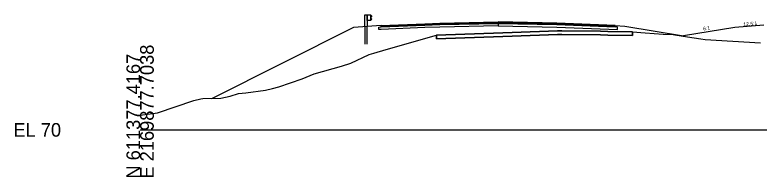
# Model space of a CAD drawing. Extents: x -26 to 1303, y -3010 to 12023.
# Drawn here: x 974.3 to 1127, y 4490.3 to 4523.6 of the extents above; entities that cross this region are included whole.
import ezdxf

# ---------------------------------------------------------------- set-up
doc = ezdxf.new("R2010")
doc.units = 0
for name, color, linetype in [('RD_GPK_XS_Cell', 7, 'Continuous'), ('RD_PD_Final_TrvlWay', 7, 'Continuous'), ('RD_XS_Base', 7, 'Continuous'), ('RD_XS_ExGround', 7, 'Continuous'), ('RD_XS_ExPaveRet', 7, 'Continuous'), ('RD_XS_GR', 7, 'Continuous'), ('RD_XS_Greenside', 7, 'Continuous'), ('RD_XS_Pave', 7, 'Continuous'), ('RD_XS_PaveOvlay_CP', 7, 'Continuous'), ('RD_XS_TieSlope', 7, 'Continuous'), ('RD_XS_TX_ShdSlope', 7, 'Continuous'), ('RD_XS_TX_Slope', 7, 'Continuous')]:
    doc.layers.add(name, color=color, linetype=linetype)

msp = doc.modelspace()

# ---------------------------------------------------------------- linework, layer by layer
at = {"layer": 'RD_GPK_XS_Cell'}
msp.add_line((1000, 4500), (1150, 4500), dxfattribs=at)
at = {"layer": 'RD_PD_Final_TrvlWay'}
msp.add_lwpolyline([(1046.58, 4517.58), (1046.58, 4521.19), (1046.08, 4521.15), (1046.08, 4517.58)], dxfattribs=at)
at = {"layer": 'RD_XS_Base'}
for p, q in [((1049.48, 4521.1), (1058.39, 4521.46)), ((1058.39, 4521.46), (1061.48, 4521.58)), ((1061.48, 4521.58), (1061.52, 4521.58)), ((1061.52, 4521.58), (1073.48, 4521.82)), ((1073.48, 4521.82), (1073.48, 4521.98)), ((1073.48, 4521.98), (1073.48, 4521.33)), ((1073.48, 4521.82), (1073.48, 4521.98)), ((1073.48, 4521.98), (1073.48, 4521.32)), ((1073.48, 4521.82), (1073.48, 4521.33)), ((1073.48, 4521.82), (1073.48, 4521.82)), ((1073.48, 4521.82), (1073.48, 4521.32)), ((1085.48, 4521.58), (1073.48, 4521.82)), ((1073.48, 4521.82), (1073.48, 4521.82)), ((1097.48, 4521.1), (1085.48, 4521.58)), ((1087.48, 4521.5), (1087.48, 4521.5)), ((1048.98, 4521.08), (1049.47, 4521.1)), ((1048.98, 4521.07), (1048.98, 4521.08)), ((1048.98, 4520.58), (1048.98, 4521.07)), ((1049.47, 4520.6), (1048.98, 4520.58)), ((1049.47, 4521.1), (1049.48, 4521.1)), ((1049.48, 4520.6), (1049.47, 4520.6)), ((1058.39, 4520.96), (1049.48, 4520.6)), ((1061.48, 4521.08), (1058.39, 4520.96)), ((1061.52, 4521.08), (1061.48, 4521.08)), ((1073.48, 4521.32), (1061.52, 4521.08)), ((1073.48, 4521.33), (1073.48, 4521.32)), ((1073.48, 4521.33), (1073.48, 4521.32)), ((1073.48, 4521.32), (1073.48, 4521.32)), ((1073.48, 4521.32), (1073.48, 4521.32)), ((1073.48, 4521.32), (1085.48, 4521.08)), ((1085.48, 4521.08), (1097.98, 4520.58)), ((1087.48, 4521), (1087.48, 4521)), ((1097.98, 4521.08), (1097.48, 4521.1)), ((1097.48, 4521.1), (1097.48, 4521.1)), ((1097.98, 4520.58), (1097.98, 4521.08)), ((1097.98, 4521.08), (1097.98, 4521.08)), ((1097.98, 4520.58), (1097.98, 4520.58)), ((1097.98, 4520.58), (1097.98, 4520.58))]:
    msp.add_line(p, q, dxfattribs=at)
at = {"layer": 'RD_XS_ExGround'}
msp.add_lwpolyline([(1000, 4502.99), (1003.56, 4503.47), (1010.99, 4505.99), (1012.44, 4506.34), (1012.87, 4506.42), (1016.59, 4506.49), (1018.48, 4506.91), (1020.22, 4507.45), (1021.7, 4507.58), (1025.74, 4508.16), (1027.17, 4508.5), (1028.48, 4508.84), (1033.22, 4510.48), (1035.7, 4511.48), (1041.34, 4513.09), (1043.24, 4513.65), (1047.03, 4515.43), (1047.96, 4515.76), (1050.51, 4516.48), (1060.82, 4519.43), (1074.39, 4519.93), (1085.61, 4520.34), (1094.43, 4520.21), (1101.04, 4520.11), (1103.6, 4519.92), (1107.34, 4519.66), (1109.39, 4519.53), (1109.73, 4519.5), (1112.34, 4519.08), (1115.03, 4518.64), (1115.93, 4518.5), (1127.3, 4517.85)], dxfattribs=at)
at = {"layer": 'RD_XS_ExPaveRet'}
for points in [[(1101.04, 4520.11), (1101.04, 4520.11), (1101.04, 4519.51), (1101.04, 4519.36), (1101.04, 4519.36), (1101.04, 4519.36), (1095.97, 4519.44), (1094.43, 4519.46), (1086.5, 4519.57), (1085.61, 4519.59), (1076.37, 4519.25), (1074.39, 4519.18), (1060.82, 4518.68), (1060.82, 4518.68), (1060.82, 4518.68), (1060.82, 4518.68), (1060.82, 4518.69), (1060.82, 4519.43), (1060.82, 4519.43), (1060.82, 4519.43), (1060.82, 4519.43), (1074.39, 4519.93), (1076.37, 4520), (1085.61, 4520.34), (1086.5, 4520.32), (1094.43, 4520.21), (1095.97, 4520.19), (1101.04, 4520.11), (1101.04, 4520.11)], [(1101.04, 4520.11), (1095.97, 4520.19), (1094.43, 4520.21), (1086.5, 4520.32), (1085.61, 4520.34), (1076.37, 4520), (1074.39, 4519.93), (1060.82, 4519.43), (1060.82, 4519.43), (1060.82, 4518.69), (1060.82, 4518.68), (1060.82, 4518.68), (1074.39, 4519.18), (1076.37, 4519.25), (1085.61, 4519.59), (1086.5, 4519.57), (1094.43, 4519.46), (1095.97, 4519.44), (1101.04, 4519.36), (1101.04, 4519.36), (1101.04, 4519.51), (1101.04, 4520.11), (1101.04, 4520.11)]]:
    msp.add_lwpolyline(points, dxfattribs=at)
at = {"layer": 'RD_XS_GR'}
for p, q in [((1046.08, 4521.15), (1046.08, 4523.58)), ((1046.08, 4523.58), (1046.33, 4523.58)), ((1046.33, 4523.58), (1046.58, 4523.58)), ((1046.58, 4523.58), (1046.58, 4521.19)), ((1046.58, 4522.41), (1046.58, 4523.58)), ((1046.58, 4523.58), (1047.25, 4523.58)), ((1047.25, 4523.58), (1047.25, 4522.41)), ((1047.25, 4523.57), (1047.25, 4523.58)), ((1047.25, 4523.58), (1047.25, 4523.56)), ((1047.52, 4523.29), (1047.25, 4523.57)), ((1047.25, 4523.56), (1047.25, 4522.41)), ((1047.25, 4523), (1047.51, 4523.28)), ((1047.25, 4522.99), (1047.25, 4523)), ((1047.52, 4522.71), (1047.25, 4522.99)), ((1047.51, 4523.28), (1047.52, 4523.29)), ((1047.25, 4522.41), (1046.58, 4522.41)), ((1047.25, 4522.41), (1047.51, 4522.7)), ((1047.51, 4522.7), (1047.52, 4522.71)), ((1046.58, 4521.19), (1046.08, 4521.15))]:
    msp.add_line(p, q, dxfattribs=at)
at = {"layer": 'RD_XS_Greenside'}
for p, q in [((1043.77, 4520.96), (1014.63, 4506.39)), ((1099.48, 4521.26), (1111.46, 4519.26)), ((1122, 4521.02), (1111.46, 4519.26))]:
    msp.add_line(p, q, dxfattribs=at)
at = {"layer": 'RD_XS_Pave'}
for p, q in [((1049.48, 4521.42), (1058.39, 4521.77)), ((1049.48, 4521.26), (1058.39, 4521.61)), ((1058.39, 4521.61), (1049.48, 4521.26)), ((1058.39, 4521.46), (1049.48, 4521.1)), ((1049.48, 4521.41), (1049.48, 4521.42)), ((1049.48, 4521.26), (1049.48, 4521.41)), ((1058.39, 4521.77), (1061.48, 4521.9)), ((1058.39, 4521.61), (1061.48, 4521.74)), ((1061.48, 4521.74), (1058.39, 4521.61)), ((1061.48, 4521.58), (1058.39, 4521.46)), ((1061.48, 4521.9), (1061.52, 4521.9)), ((1061.48, 4521.74), (1061.52, 4521.74)), ((1061.52, 4521.74), (1061.48, 4521.74)), ((1061.52, 4521.58), (1061.48, 4521.58)), ((1061.52, 4521.9), (1073.48, 4522.14)), ((1061.52, 4521.74), (1073.48, 4521.98)), ((1073.48, 4521.98), (1061.52, 4521.74)), ((1073.48, 4521.82), (1061.52, 4521.58)), ((1085.48, 4521.9), (1073.48, 4522.14)), ((1073.48, 4521.98), (1073.48, 4521.82)), ((1073.48, 4521.98), (1073.48, 4521.82)), ((1073.48, 4521.82), (1073.48, 4521.98)), ((1073.48, 4521.98), (1085.48, 4521.74)), ((1085.48, 4521.74), (1073.48, 4521.98)), ((1073.48, 4521.98), (1073.48, 4521.82)), ((1073.48, 4521.82), (1073.48, 4521.82)), ((1073.48, 4521.82), (1073.48, 4521.82)), ((1073.48, 4521.82), (1073.48, 4521.82)), ((1073.48, 4521.82), (1073.48, 4521.82)), ((1073.48, 4521.82), (1085.48, 4521.58)), ((1097.48, 4521.42), (1085.48, 4521.9)), ((1085.48, 4521.74), (1097.48, 4521.26)), ((1097.48, 4521.26), (1085.48, 4521.74)), ((1085.48, 4521.58), (1097.48, 4521.1)), ((1087.48, 4521.82), (1087.48, 4521.82)), ((1087.48, 4521.66), (1087.48, 4521.66)), ((1087.48, 4521.66), (1087.48, 4521.66)), ((1087.48, 4521.5), (1087.48, 4521.5)), ((1097.48, 4521.26), (1097.48, 4521.42)), ((1097.48, 4521.42), (1097.48, 4521.42)), ((1049.48, 4521.1), (1049.48, 4521.26)), ((1049.48, 4521.26), (1049.48, 4521.26)), ((1097.48, 4521.26), (1097.48, 4521.26)), ((1097.48, 4521.26), (1097.48, 4521.26)), ((1097.48, 4521.1), (1097.48, 4521.26)), ((1097.48, 4521.26), (1097.48, 4521.26)), ((1097.48, 4521.1), (1097.48, 4521.1)), ((1097.48, 4521.1), (1097.48, 4521.1))]:
    msp.add_line(p, q, dxfattribs=at)
at = {"layer": 'RD_XS_PaveOvlay_CP'}
for p, q in [((1049.48, 4521.42), (1058.39, 4521.77)), ((1058.39, 4521.77), (1061.48, 4521.9)), ((1061.48, 4521.9), (1073.48, 4522.14)), ((1073.48, 4522.14), (1085.48, 4521.9)), ((1085.48, 4521.9), (1097.48, 4521.42))]:
    msp.add_line(p, q, dxfattribs=at)
at = {"layer": 'RD_XS_TieSlope'}
for p, q in [((1049.48, 4521.42), (1043.77, 4520.96)), ((1097.48, 4521.42), (1099.48, 4521.26)), ((1128, 4521.5), (1122, 4521.02))]:
    msp.add_line(p, q, dxfattribs=at)

# ---------------------------------------------------------------- texts
at = {"layer": 'RD_GPK_XS_Cell'}
for s, p in [('E 2169877.7038', (1002.8, 4490)), ('N 611377.4167', (1000, 4490))]:
    msp.add_text(s, height=2.8, rotation=90, dxfattribs=at).set_placement(p)
msp.add_text('EL 70', height=2.8, dxfattribs=at).set_placement((974, 4498.6))
at = {"layer": 'RD_XS_TX_ShdSlope'}
msp.add_text('12.5:1', height=0.75, rotation=4.5739, dxfattribs=at).set_placement((1123.78, 4521.27))
at = {"layer": 'RD_XS_TX_Slope'}
msp.add_text('6:1', height=0.75, rotation=9.4642, dxfattribs=at).set_placement((1115.57, 4520.36))

doc.saveas('drawing.dxf')
